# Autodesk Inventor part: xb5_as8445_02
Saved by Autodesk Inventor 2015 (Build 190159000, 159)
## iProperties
Created: 2018-04
Part Number: xb5_as8445_02
Checked By: TraceParts S.A.
Material: Generic
Catalog Web Link: www.traceparts.com
Document SubType Name: Modeling
Designer: TraceParts
Density: 1 g/cm^3
Appearance: Default
Company: TraceParts S.A.
Author: TraceParts
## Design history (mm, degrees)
feature "xb5_as8445_02.ipt"
body "Solid1"
